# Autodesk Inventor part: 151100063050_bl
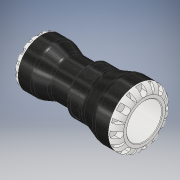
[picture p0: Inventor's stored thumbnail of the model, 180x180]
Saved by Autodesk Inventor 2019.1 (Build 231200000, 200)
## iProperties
Created: 2016-12
Part Number: 151100063050_bl
Material: PVC-Piping
Description: PLASSON G-PLASS  REDUCING COUPLING  63 x 50
Document SubType Name: Modeling
Designer: KIM
Mass: 309.689 g
Surface Area: 488.063 cm^2
Volume: 221.206 cm^3
Density: 1.4 g/cm^3
Appearance: Black Cast
Author: KIM
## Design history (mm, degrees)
derived "151100.ipt"
feature "Solid1::151100.ipt" dims "ScaleForDerivedMember" = 10
tag "TaggingFeature1"
body "Solid1"
other parameters: "d_" = 63 [user parameter], "E_" = 103 [user parameter], "H_" = 196 [user parameter], "l_" = 96 [user parameter], "E1" = 85 [user parameter], "l1" = 85 [user parameter], "Plasson" = 1 [user parameter], "d20" = 11.25 [user parameter], "d21" = 13.7 [user parameter], "d23" = 103 [user parameter], "d24" = 75.6 [user parameter], "d40" = 85 [user parameter], "d41" = 62.5 [user parameter], "d59" = 24.97398 [user parameter], "d0" = 196 [user parameter], "d2" = 40.32 [user parameter], "d3" = 63 [user parameter], "d4" = 103 [user parameter], "d5" = 75.6 [user parameter], "d6" = 96 [user parameter], "d7" = 5.25 [user parameter], "d8" = 85 [user parameter], "d10" = 62.5 [user parameter], "d11" = 35.7 [user parameter], "d12" = 85 [user parameter], "d13" = 4.16667 [user parameter], "d14" = 82.4 [user parameter], "d15" = 68 [user parameter], "d16" = 20 deg [user parameter], "d17" = 20 deg [user parameter], "d18" = 130 deg [user parameter], "d22" = 10.96 [user parameter], "d25" = 10.96 [user parameter], "d26" = 0 [user parameter], "d28" = 360 deg [user parameter], "d30" = 8 deg [user parameter], "d31" = 1.26 [user parameter], "d32" = 8 deg [user parameter], "d33" = 1.26 [user parameter], "d35" = 0 [user parameter], "d37" = 360 deg [user parameter], "d39" = 9 [user parameter], "d42" = 9 [user parameter], "d43" = 0 [user parameter], "d45" = 360 deg [user parameter], "d47" = 1 [user parameter], "d48" = 8 deg [user parameter], "d49" = 8 deg [user parameter], "d50" = 1 [user parameter], "d52" = 0 [user parameter], "d54" = 360 deg [user parameter], "d56" = 17 [user parameter], "d57" = 20.6 [user parameter], "d58" = 0.5 [user parameter], "d60" = 12.36 [user parameter], "d61" = 15.75 [user parameter], "d62" = 17.46 [user parameter], "d63" = 0 [user parameter], "d66" = 0 [user parameter], "d68" = 360 deg [user parameter], "d75" = 12.48699 [user parameter], "d77" = 80.34 [user parameter], "d78" = 1.03 [user parameter]
